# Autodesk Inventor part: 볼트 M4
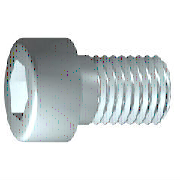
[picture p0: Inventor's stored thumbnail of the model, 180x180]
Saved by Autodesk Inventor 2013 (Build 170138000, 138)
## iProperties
IsCustomPart: 1
Created: 2012-02
Part Number: 볼트 M4
Material: 강철, 연강
Description: 6각머리 태핑 나사
Document SubType Name: Modeling
Standard: KS B 1003
Designer: test
Standards Organization: KS
Language: ko-KR
Size Designation: M 4 x 10
Categories: <MemberInstance><Categories><Category DisplayName="조임쇠" InternalName="e4da775c-781d-43d5-af7c-5136215cf5a6" Mnemonic="FSTN"><Category DisplayName="볼트" InternalN
Density: 1 g/cm^3
Author: test
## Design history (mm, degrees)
sketch "스케치1"
  geometry: L1 (-1, 0)-(10, 0); L2 (10, 0)-(10, 2); L3 (10, 2)-(1.75, 2); L4 (1.75, 2)-(1.32, 2); L5 (1.32, 2)-(0, 2); L6 (0, 2)-(0, 3.5); L7 (0, 3.5)-(-4, 3.5); L8 (-4, 3.5)-(-4, 1.732); L9 (-4, 1.732)-(-2, 1.732); L10 (-2, 1.732)-(-1, 0); L11 (-6.8, 0)-(12.8, 0) reference; L12 (0, -0.7)-(0, 4.2) reference; L13 (1.75, 2)-(0, 2)
  constraints: 22 end point, 6 parallel, 2 collinear, 2 perpendicular, 1 horizontal, 1 point on line
  dimensions: "d1" = 8.25 distance from line of L3.end L2 (= GEL); "d2" = 0.42952 distance of L4.end L3.end (computed from GAL); "d3" = 4 distance between parallel lines of L8 L6 (= KOH); "d4" = 2 distance of L8.end L9.end (= INTI); "d5" = 60 deg angle of L10 L1; "d6" = 4 diameter of L3 L1 (= GD); "d7" = 4 diameter of L5 L1 (= BDM); "d8" = 3.4641 diameter of L9 L1 (= 1.1547 x SW); "d9" = 7 diameter of L7 L1 (= KOD); "d26" = 10 distance between parallel lines of L12 L2 (= NLG)
revolve "본체" sketch "스케치1" stored, may be unused: angle "d10" = 90 deg
sketch "스케치2"
  geometry: L1 (0, -4.9)-(0, 4.9) reference; L2 (-4.9, 0)-(4.9, 0) reference; L3 (1.732, 0)-(0.866, -1.5); L4 (0.866, -1.5)-(-0.866, -1.5); L5 (-0.866, -1.5)-(-1.732, 0); L6 (-1.732, 0)-(-0.866, 1.5); L7 (-0.866, 1.5)-(0.866, 1.5); L8 (0.866, 1.5)-(1.732, 0); 2 further points
  constraints: 12 end point, 1 coincident, 1 horizontal alignment, 1 point on line, 12 other
extrude "슬롯" join sketch "스케치2" stored distance "d11" = 10; taper "d12" = 0 deg
workplane "Work Plane1"
fillet "Fillet2" dims "d30" = 0.1 (= R)
body "Solid1"
fillet "모깎기1" dims "d17" = 0.4 (= RR)
feature "스레드" dims "d13" = 8.25 (= GEL), "d14" = 0
chamfer "모따기1" distance "d15" = 0.42941 (= -0.5 x SPD + 0.5 x GD); stored, may be unused: second distance "d16" = 0.42941 (= GUL), angle "d27" = 45 deg
other parameters: "GD" = 4 (= NND) [user parameter; used in 2 equation terms], "NLG" = 10 [user parameter; used in 1 equation term], "GEL" = 8.25 [user parameter; used in 2 equation terms], "KOD" = 7 [user parameter; used in 1 equation term], "KOH" = 4 [user parameter; used in 1 equation term], "INTI" = 2 [user parameter; used in 1 equation term], "GAL" = 0.42941 (= 0.61345 x PTC) [user parameter; used in 1 equation term], "GUL" = 0.42941 (= 0.61345 x PTC) [user parameter; used in 1 equation term], "BDM" = 4 (= NND) [user parameter; used in 1 equation term], "SW" = 3 [user parameter; used in 2 equation terms], "RR" = 0.4 [user parameter; used in 1 equation term], "SPD" = 3.14117 (= NND - 1.2269 x PTC) [user parameter; used in 1 equation term], "d19" = 0, "d28" = 0, "d29" = 0, "R" = 0.1 [user parameter; used in 1 equation term], "PHH" = 0.2 [user parameter], "GD1" = 3.14117 (= THREADDIA - 1.2269 x PTC) [user parameter], "THREADDIA" = 4 [user parameter; used in 1 equation term], "FAWI" = 45 deg [user parameter], "TPU" = 14.28571 (computed from PTC) [user parameter], "PTC" = 0.7 [user parameter; used in 5 equation terms], "NND" = 4 [user parameter; used in 3 equation terms], "TOA" = 30 deg [user parameter], "E0" = 3.465 (= 1.155 x SW) [user parameter]
